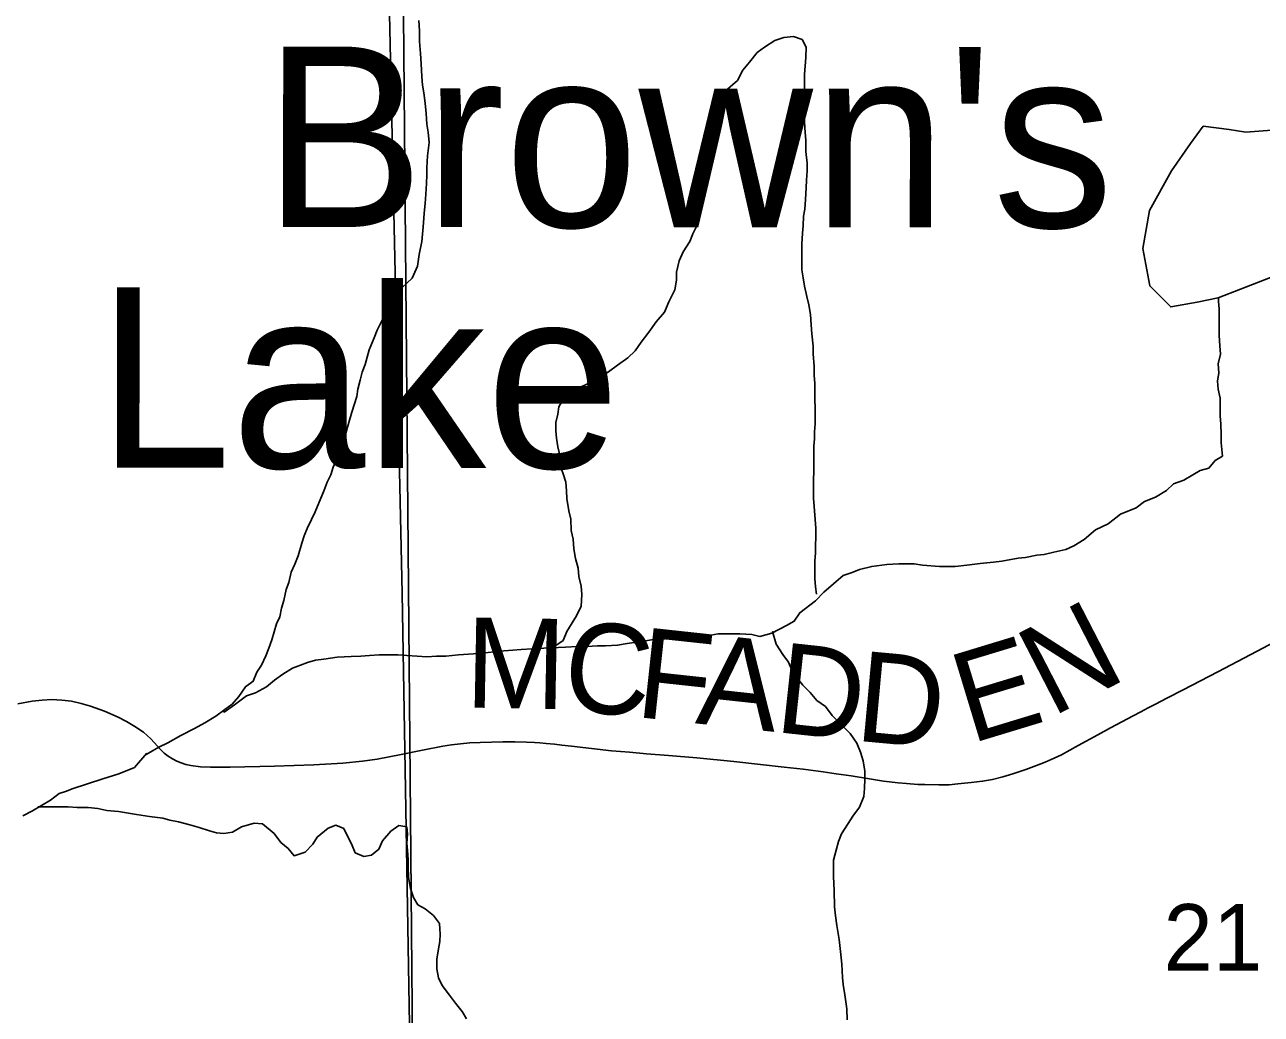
# Model space of a CAD drawing. Extents: x 0 to 34, y 0 to 22.
# Drawn here: x 5.258 to 6.037, y 14.723 to 15.347 of the extents above; entities that cross this region are included whole.
import ezdxf

# ---------------------------------------------------------------- set-up
doc = ezdxf.new("R2010")
doc.units = 0
for name, color, linetype in [('GM_X_Minor_Lake', 7, 'Continuous'), ('GM_X_Minor_Lake_Text', 7, 'Continuous'), ('GM_X_Minor_River', 7, 'Continuous'), ('GM_X_Rail_Line', 7, 'Continuous'), ('GM_X_Section', 7, 'Continuous'), ('GM_X_Section_Text', 7, 'Continuous'), ('GM_X_Township_Road', 7, 'Continuous'), ('GM_X_Township_Road_Text', 7, 'Continuous')]:
    doc.layers.add(name, color=color, linetype=linetype)

msp = doc.modelspace()

# ---------------------------------------------------------------- linework, layer by layer
at = {"layer": 'GM_X_Minor_Lake'}
msp.add_lwpolyline([(6.08096, 15.23104), (6.07445, 15.25038), (6.06567, 15.26743), (6.05502, 15.27878), (6.04403, 15.28026), (6.02775, 15.27907), (6.01714, 15.28055), (6.00084, 15.28278), (5.99293, 15.27174), (5.98087, 15.25463), (5.96695, 15.22953), (5.96287, 15.20561), (5.96713, 15.18209), (5.98044, 15.16885), (5.99709, 15.17194), (6.01034, 15.17464), (6.02433, 15.18), (6.05459, 15.19187)], dxfattribs=at)
at = {"layer": 'GM_X_Minor_River'}
for points in [[(5.50638, 15.34934), (5.50677, 15.34288), (5.50679, 15.33603), (5.50757, 15.32843), (5.50797, 15.32196), (5.50837, 15.31398), (5.50876, 15.30866), (5.50954, 15.30371), (5.51032, 15.29725), (5.51109, 15.29078), (5.51149, 15.28394), (5.51226, 15.27899), (5.51304, 15.27253), (5.51192, 15.26416), (5.51155, 15.25656), (5.51157, 15.252), (5.51119, 15.24667), (5.51083, 15.23983), (5.51046, 15.23413), (5.50971, 15.22804), (5.50934, 15.22196), (5.50898, 15.21702), (5.50823, 15.21017), (5.50672, 15.20181), (5.50559, 15.19458), (5.50218, 15.18698), (5.4957, 15.1809), (5.4919, 15.17558), (5.48657, 15.16722), (5.48278, 15.15923), (5.48012, 15.15429), (5.47822, 15.14935), (5.47519, 15.14175), (5.47253, 15.13262), (5.47064, 15.12768), (5.46951, 15.12274), (5.46799, 15.11704), (5.46724, 15.11247), (5.46421, 15.10259), (5.46232, 15.09613), (5.46042, 15.08928), (5.45701, 15.07978), (5.45474, 15.07332), (5.45246, 15.06799), (5.45094, 15.06305), (5.44866, 15.05849), (5.44677, 15.05355), (5.44108, 15.03986), (5.4388, 15.03492), (5.43614, 15.02922), (5.43424, 15.02466), (5.43273, 15.02009), (5.43045, 15.01211), (5.42818, 15.00679), (5.4259, 15.00185), (5.42439, 14.99538), (5.42287, 14.99082), (5.42136, 14.98398), (5.41985, 14.97904), (5.41871, 14.97371), (5.41681, 14.96915), (5.41379, 14.95927), (5.41189, 14.95395), (5.40999, 14.949)], [(5.5909, 14.95427), (5.59735, 14.95878), (5.59963, 14.96448), (5.60305, 14.9698), (5.60571, 14.97436), (5.60875, 14.98045), (5.60912, 14.98767), (5.60872, 14.99299), (5.60718, 14.99908), (5.60679, 15.0044), (5.60525, 15.01049), (5.60409, 15.01657), (5.60369, 15.02266), (5.60253, 15.02798), (5.60214, 15.0352), (5.60098, 15.04053), (5.59982, 15.04813), (5.59942, 15.05308), (5.59903, 15.0584), (5.59749, 15.06373), (5.59557, 15.06905), (5.59517, 15.07627), (5.59402, 15.08084), (5.59324, 15.08616), (5.59285, 15.09073), (5.59284, 15.09605), (5.59397, 15.10137), (5.59472, 15.10594), (5.59738, 15.11087), (5.60233, 15.11544), (5.60919, 15.11885), (5.61415, 15.12113), (5.61987, 15.12417), (5.62596, 15.12797), (5.63168, 15.13215), (5.63815, 15.13671), (5.64273, 15.14127), (5.64653, 15.14659), (5.65147, 15.15305), (5.65604, 15.15951), (5.66137, 15.16559), (5.66402, 15.17206), (5.66782, 15.17966), (5.66895, 15.18574), (5.66894, 15.19069), (5.67045, 15.19791), (5.67311, 15.20361), (5.67729, 15.21007), (5.67919, 15.21502), (5.68147, 15.21958), (5.68336, 15.22566), (5.6845, 15.23022), (5.68563, 15.23592), (5.68676, 15.24201), (5.68751, 15.24733), (5.68788, 15.25227), (5.68863, 15.25798), (5.68976, 15.2633), (5.69127, 15.26938), (5.69317, 15.27585), (5.6943, 15.28307), (5.69429, 15.28801), (5.69504, 15.29296), (5.69731, 15.29904), (5.69959, 15.30474), (5.70721, 15.31158), (5.71062, 15.31804), (5.71481, 15.32298), (5.71976, 15.32906), (5.72433, 15.33248), (5.73081, 15.33666), (5.73653, 15.33856), (5.74263, 15.33932), (5.74798, 15.33741), (5.75066, 15.33247), (5.7503, 15.32601), (5.74956, 15.31536), (5.74958, 15.30623), (5.74921, 15.30053), (5.74923, 15.29102), (5.74963, 15.28532), (5.75003, 15.27886), (5.75042, 15.27391), (5.75044, 15.26669), (5.75122, 15.25946), (5.75123, 15.25452), (5.75086, 15.24881), (5.75049, 15.24387), (5.75012, 15.23665), (5.74976, 15.23056), (5.749, 15.226), (5.74864, 15.21992), (5.74827, 15.21536), (5.7479, 15.20851), (5.74794, 15.19216), (5.74871, 15.18722), (5.74949, 15.18189), (5.75103, 15.17543), (5.75219, 15.1701), (5.75334, 15.16402), (5.75374, 15.15755)], [(6.01145, 15.11139), (6.0103, 15.1171), (6.0099, 15.12204), (6.01065, 15.12736), (6.01026, 15.13307), (6.01177, 15.13915), (6.01138, 15.14447), (6.01098, 15.15094), (6.01094, 15.16767), (6.01055, 15.17223), (6.01054, 15.17472)], [(5.75374, 15.15755), (5.75414, 15.15185), (5.75492, 15.14424), (5.75493, 15.1393), (5.75571, 15.13132), (5.75572, 15.12599), (5.75612, 15.12067), (5.75618, 15.09519), (5.75581, 15.09025), (5.75582, 15.08569), (5.75545, 15.08112), (5.75546, 15.07618), (5.75547, 15.07048), (5.75548, 15.06553), (5.75512, 15.05945), (5.75514, 15.04842), (5.75554, 15.0431), (5.75671, 15.02941), (5.75673, 15.02371), (5.75636, 15.01876), (5.75637, 15.01382), (5.756, 15.00888), (5.75602, 14.99785), (5.75642, 14.99253), (5.75719, 14.98796)], [(5.38315, 14.91447), (5.38374, 14.91366), (5.39022, 14.91822), (5.39784, 14.92391), (5.40356, 14.92581), (5.41042, 14.92961), (5.41537, 14.93379), (5.4207, 14.93759), (5.4268, 14.94139), (5.43176, 14.94329), (5.43633, 14.94481), (5.44129, 14.94632), (5.44664, 14.94708), (5.45503, 14.94822), (5.4638, 14.94859), (5.46991, 14.94897), (5.47525, 14.94934), (5.48136, 14.94972), (5.49319, 14.94971), (5.49891, 14.94933), (5.5054, 14.94895), (5.51151, 14.94856), (5.51762, 14.94894), (5.52334, 14.94894), (5.53135, 14.94969), (5.54089, 14.95045), (5.55005, 14.9512), (5.5573, 14.95196), (5.56569, 14.95271), (5.57103, 14.95309), (5.5779, 14.95347), (5.58515, 14.95384), (5.58973, 14.95422), (5.59889, 14.9546), (5.60614, 14.95497), (5.61225, 14.95497), (5.61912, 14.95534), (5.62408, 14.95534), (5.63171, 14.95572), (5.63781, 14.95685), (5.64354, 14.95761), (5.64811, 14.95837), (5.65307, 14.95912), (5.65956, 14.9595), (5.66643, 14.96026), (5.67101, 14.96026), (5.67826, 14.96063), (5.68398, 14.96139), (5.69047, 14.96215), (5.69504, 14.9629), (5.70878, 14.9629), (5.71642, 14.96251), (5.72138, 14.96137), (5.72901, 14.96327), (5.73816, 14.9682), (5.74311, 14.97086), (5.74653, 14.97618), (5.75644, 14.98378), (5.76177, 14.9891), (5.77396, 14.99974), (5.77968, 15.00164), (5.78425, 15.00354), (5.79188, 15.00543), (5.80142, 15.00657), (5.80905, 15.00695), (5.81859, 15.00694), (5.82394, 15.00618), (5.83462, 15.00541), (5.84455, 15.0054), (5.8518, 15.00616), (5.86019, 15.00729), (5.86858, 15.00805), (5.87392, 15.00881), (5.88422, 15.0107), (5.8888, 15.01108), (5.89605, 15.0126), (5.90063, 15.01297), (5.90673, 15.01449), (5.91436, 15.01601), (5.91932, 15.01829), (5.9258, 15.02247), (5.93303, 15.02855), (5.94104, 15.03234), (5.94865, 15.03842), (5.95857, 15.04222), (5.9639, 15.0464), (5.97076, 15.04905), (5.97763, 15.05323), (5.9822, 15.05741), (5.98868, 15.05969), (5.9944, 15.06311), (5.99897, 15.06577), (6.00431, 15.06729), (6.00849, 15.07223), (6.01307, 15.07489), (6.01228, 15.08325), (6.01227, 15.08858), (6.01188, 15.09504), (6.01148, 15.10037), (6.01147, 15.10607), (6.01145, 15.11139)], [(5.72978, 14.96368), (5.72939, 14.96441), (5.7317, 14.95642), (5.73591, 14.94995), (5.73936, 14.94501), (5.74127, 14.94044), (5.74434, 14.93588), (5.74855, 14.93055), (5.75314, 14.92599), (5.75735, 14.92104), (5.7627, 14.91723), (5.76691, 14.91153), (5.77839, 14.90012), (5.7826, 14.89403), (5.7849, 14.88832), (5.78644, 14.883), (5.7876, 14.87653), (5.78761, 14.87159), (5.78725, 14.86551), (5.78688, 14.86056), (5.78422, 14.85372), (5.78004, 14.84802), (5.77699, 14.84346), (5.77281, 14.837), (5.77091, 14.83205), (5.7694, 14.82673), (5.76789, 14.82027), (5.76791, 14.81), (5.76831, 14.80126), (5.76834, 14.79099), (5.76912, 14.78529), (5.76989, 14.7792), (5.77144, 14.77046), (5.77222, 14.76285), (5.773, 14.75487), (5.7734, 14.7465), (5.7738, 14.74194), (5.77496, 14.73547), (5.77612, 14.72673), (5.77652, 14.71988)], [(5.40999, 14.949), (5.40733, 14.9433), (5.40429, 14.93874), (5.40201, 14.93304), (5.39706, 14.92962), (5.39288, 14.92354), (5.38869, 14.9186), (5.38412, 14.91518), (5.3784, 14.911), (5.37155, 14.90682), (5.36507, 14.9034), (5.3563, 14.89884), (5.3483, 14.89429), (5.34258, 14.89163), (5.3361, 14.88783), (5.33459, 14.88693)], [(5.28783, 14.86527), (5.30715, 14.8717), (5.31725, 14.87472), (5.32717, 14.87879), (5.33497, 14.88783)], [(5.28783, 14.86527), (5.28425, 14.8639), (5.27968, 14.86238), (5.27434, 14.85821), (5.26291, 14.85137), (5.25681, 14.84833)], [(5.26634, 14.85403), (5.28542, 14.85402), (5.29115, 14.85363), (5.29801, 14.85363), (5.30412, 14.85286), (5.30985, 14.85172), (5.3171, 14.85096), (5.32207, 14.85019), (5.32856, 14.84905), (5.33657, 14.8479), (5.34497, 14.84676), (5.34955, 14.84561), (5.3549, 14.84447), (5.36216, 14.84256), (5.36788, 14.84104), (5.37438, 14.83875), (5.37896, 14.83761), (5.38354, 14.83723), (5.38888, 14.83799), (5.3946, 14.84141), (5.40261, 14.84368), (5.40795, 14.8433), (5.41522, 14.83721), (5.41943, 14.8315), (5.42401, 14.8277), (5.42784, 14.82313), (5.43471, 14.82541), (5.43966, 14.83035), (5.44232, 14.83491), (5.44917, 14.84061), (5.45413, 14.84251), (5.4591, 14.84023), (5.46446, 14.82958), (5.46638, 14.82501), (5.47173, 14.82273), (5.47669, 14.82348), (5.48126, 14.82729), (5.48354, 14.83261), (5.48887, 14.83869), (5.49382, 14.84211), (5.49879, 14.84134), (5.49918, 14.83678), (5.49881, 14.83108), (5.4992, 14.82651), (5.4996, 14.82081), (5.49961, 14.81625), (5.5, 14.8094), (5.50116, 14.80256), (5.50309, 14.79685), (5.50577, 14.79229), (5.51036, 14.78962), (5.51571, 14.78544), (5.51954, 14.78049), (5.51993, 14.77365), (5.51956, 14.76909), (5.51881, 14.76452), (5.51768, 14.75806), (5.51769, 14.75198), (5.51885, 14.74627), (5.52115, 14.74133), (5.52575, 14.73524), (5.52958, 14.7303), (5.53379, 14.72497), (5.53647, 14.72041)]]:
    msp.add_lwpolyline(points, dxfattribs=at)
at = {"layer": 'GM_X_Rail_Line'}
msp.add_lwpolyline([(5.88863, 16.83347), (5.72006, 16.39003), (5.49797, 15.81639), (5.48598, 15.77743), (5.48054, 15.734), (5.48036, 15.69941), (5.49584, 14.98866), (5.50116, 14.67953)], dxfattribs=at)
at = {"layer": 'GM_X_Section'}
for points in [[(5.49662, 15.37719), (6.00137, 15.38987), (6.50804, 15.39727), (6.51868, 14.37863), (5.50533, 14.36709)], [(4.46211, 15.35397), (5.37649, 15.3766), (5.49662, 15.37719), (5.50533, 14.36709), (4.47378, 14.3535)]]:
    msp.add_lwpolyline(points, close=True, dxfattribs=at)
at = {"layer": 'GM_X_Township_Road'}
msp.add_lwpolyline([(5.25359, 14.91888), (5.26273, 14.92055), (5.2689, 14.92122), (5.27511, 14.92149), (5.28131, 14.92126), (5.28747, 14.92046), (5.29354, 14.91916), (5.29953, 14.91746), (5.30831, 14.91432), (5.31685, 14.91053), (5.32216, 14.90767), (5.32739, 14.90464), (5.33282, 14.90093), (5.33525, 14.899), (5.33752, 14.89689), (5.34371, 14.88993), (5.346, 14.88785), (5.34846, 14.88595), (5.35107, 14.88427), (5.35382, 14.88282), (5.35669, 14.88163), (5.35965, 14.88071), (5.36268, 14.88002), (5.36884, 14.87923), (5.37504, 14.87886), (5.38746, 14.87886), (5.41543, 14.87951), (5.44019, 14.88042), (5.4585, 14.88147), (5.47084, 14.88264), (5.48008, 14.88394), (5.49532, 14.88695), (5.50867, 14.88957), (5.52149, 14.89213), (5.52697, 14.89295), (5.53266, 14.89367), (5.5385, 14.89423), (5.54502, 14.89458), (5.55947, 14.89492), (5.56703, 14.89499), (5.57424, 14.89477), (5.57938, 14.89452), (5.58277, 14.89422), (5.58665, 14.89388), (5.59186, 14.89343), (5.59663, 14.89288), (5.60273, 14.89222), (5.62789, 14.88933), (5.63932, 14.88833), (5.64996, 14.88733), (5.66382, 14.88622), (5.68166, 14.88477), (5.70506, 14.88244), (5.7218, 14.88066), (5.73677, 14.879), (5.74874, 14.87767), (5.76138, 14.876), (5.76947, 14.87478), (5.779, 14.87345), (5.78931, 14.87178), (5.79941, 14.87023), (5.8086, 14.86912), (5.81393, 14.86857), (5.82102, 14.86812), (5.82545, 14.86801), (5.83421, 14.86778), (5.84075, 14.86789), (5.84608, 14.86845), (5.8545, 14.86922), (5.86182, 14.87011), (5.86803, 14.87121), (5.87446, 14.87277), (5.88078, 14.87465), (5.88909, 14.87742), (5.89585, 14.87997), (5.90118, 14.88207), (5.90695, 14.88462), (5.91149, 14.88673), (5.92202, 14.8926), (5.93433, 14.89936), (5.94237, 14.90367), (5.95318, 14.90945), (5.95662, 14.91133), (5.96161, 14.91388), (5.96615, 14.91632), (5.97081, 14.91865), (5.97801, 14.92241), (5.98821, 14.92763), (6.01006, 14.93904), (6.03478, 14.95201), (6.06039, 14.96553)], dxfattribs=at)

# ---------------------------------------------------------------- texts
at = {"layer": 'GM_X_Minor_Lake_Text'}
for s, rotation, p in [("Brown's ", 359.96608, (5.40839, 15.21927)), ('Lake', 359.96583, (5.30368, 15.06759))]:
    msp.add_text(s, height=0.113663, rotation=rotation, dxfattribs=at).set_placement(p)
at = {"layer": 'GM_X_Section_Text'}
msp.add_text('21', height=0.041856, rotation=0.00001, dxfattribs=at).set_placement((5.97581, 14.75083))
at = {"layer": 'GM_X_Township_Road_Text'}
for s, rotation, p in [('N', 27.26778, (5.90523, 14.91014)), ('M', 358.97357, (5.53541, 14.91654)), ('C', 354.09406, (5.59579, 14.91552)), ('F', 353.82772, (5.64214, 14.91072)), ('A', 353.82273, (5.68025, 14.9066)), ('E', 16.90593, (5.85418, 14.89357)), ('D', 353.83373, (5.72997, 14.90122)), ('D', 354.72049, (5.78064, 14.89575))]:
    msp.add_text(s, height=0.05682, rotation=rotation, dxfattribs=at).set_placement(p)

doc.saveas('drawing.dxf')
